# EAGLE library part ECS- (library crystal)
CRYSTAL FILTERS Source: http://www.presto.co.uk
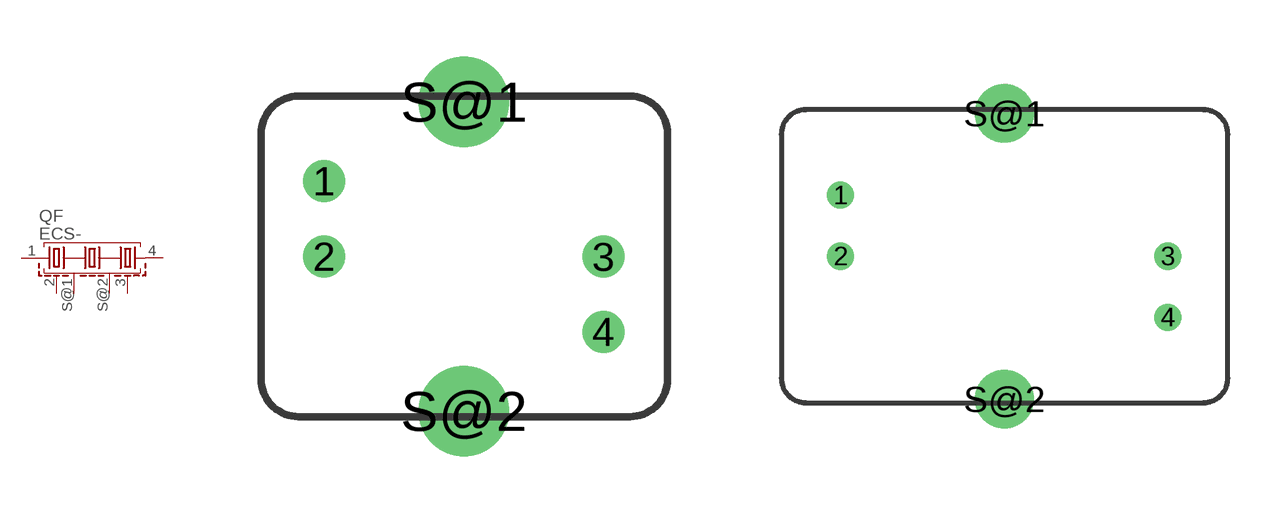
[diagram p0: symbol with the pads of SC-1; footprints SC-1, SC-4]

Designator prefix QF

## ECS-21K30D (OC_FARNELL: unknown; OC_NEWARK: unknown)  [SC-1]
1  1  pas
2  2  pas
3  3  pas
4  4  pas
S@1  S  pas
S@2  S  pas

## ECS-21K30C (OC_FARNELL: unknown; OC_NEWARK: unknown)  [SC-1]
Pads as for SC-1

## ECS-10.7-30D (OC_FARNELL: unknown; OC_NEWARK: unknown)  [SC-4]
Pads as for SC-1

## ECS-10.7-30C (OC_FARNELL: unknown; OC_NEWARK: unknown)  [SC-3]
Pads as for SC-1

## ECS-21K15E (OC_FARNELL: unknown; OC_NEWARK: unknown)  [SC-2]
Pads as for SC-1

## ECS-21K15D (OC_FARNELL: unknown; OC_NEWARK: unknown)  [SC-1]
Pads as for SC-1

## ECS-21K15C (OC_FARNELL: unknown; OC_NEWARK: unknown)  [SC-1]
Pads as for SC-1

## ECS-10.7-15E (OC_FARNELL: unknown; OC_NEWARK: unknown)  [SC-5]
Pads as for SC-1

## ECS-10.7-15D (OC_FARNELL: unknown; OC_NEWARK: unknown)  [SC-4]
Pads as for SC-1

## ECS-10.7-15C (OC_FARNELL: unknown; OC_NEWARK: unknown)  [SC-3]
Pads as for SC-1

## ECS-21K12D (OC_FARNELL: unknown; OC_NEWARK: unknown)  [SC-1]
Pads as for SC-1

## ECS-21K12C (OC_FARNELL: unknown; OC_NEWARK: unknown)  [SC-1]
Pads as for SC-1

## ECS-21K7.5E (OC_FARNELL: unknown; OC_NEWARK: unknown)  [SC-2]
Pads as for SC-1

## ECS-21K7.5D (OC_FARNELL: unknown; OC_NEWARK: unknown)  [SC-1]
Pads as for SC-1

## ECS-21K7.5C (OC_FARNELL: unknown; OC_NEWARK: unknown)  [SC-1]
Pads as for SC-1

## ECS-10.7-7.5D (OC_FARNELL: unknown; OC_NEWARK: unknown)  [SC-4]
Pads as for SC-1

## ECS-10.7-7.5C (OC_FARNELL: unknown; OC_NEWARK: unknown)  [SC-3]
Pads as for SC-1

## Footprint SC-1 (pad centres in mm)
CRYSTAL FILTERS Source: http://www.presto.co.uk
drill 0.6 pad 1.016 round: 1 -3.7,2; 2 -3.7,0; 3 3.7,0; 4 3.7,-2
drill 1.6 pad 1.93 round: S@1 0,4.1; S@2 0,-4.1

## Footprint SC-4 (pad centres in mm)
CRYSTAL FILTERS Source: http://www.presto.co.uk
drill 0.6 pad 1.016 round: 1 -6.7,2.5; 2 -6.7,0; 3 6.7,0; 4 6.7,-2.5
drill 1.6 pad 1.93 round: S@1 0,5.85; S@2 0,-5.85

## Footprint SC-3 (pad centres in mm)
CRYSTAL FILTERS Source: http://www.presto.co.uk
drill 0.6 pad 1.016 round: 1 -4.5,2.5; 2 -4.5,0; 3 4.5,0; 4 4.5,-2.5
drill 1.6 pad 1.93 round: S@1 0,5.85; S@2 0,-5.85

## Footprint SC-2 (pad centres in mm)
CRYSTAL FILTERS Source: http://www.presto.co.uk
drill 0.6 pad 1.016 round: 1 -4.9,2; 2 -4.9,0; 3 4.9,0; 4 4.9,-2
drill 1.6 pad 1.93 round: S@1 0,4.1; S@2 0,-4.1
